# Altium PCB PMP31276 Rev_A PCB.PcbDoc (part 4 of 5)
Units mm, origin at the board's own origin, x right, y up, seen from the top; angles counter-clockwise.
Board outline 228.6 x 203.2 mm, 4 copper layers (Top Layer, Layer 1, Layer 2, Bottom Layer), stack 1.998 mm thick; 375 components, 187 nets, 994 pads, 546 vias.
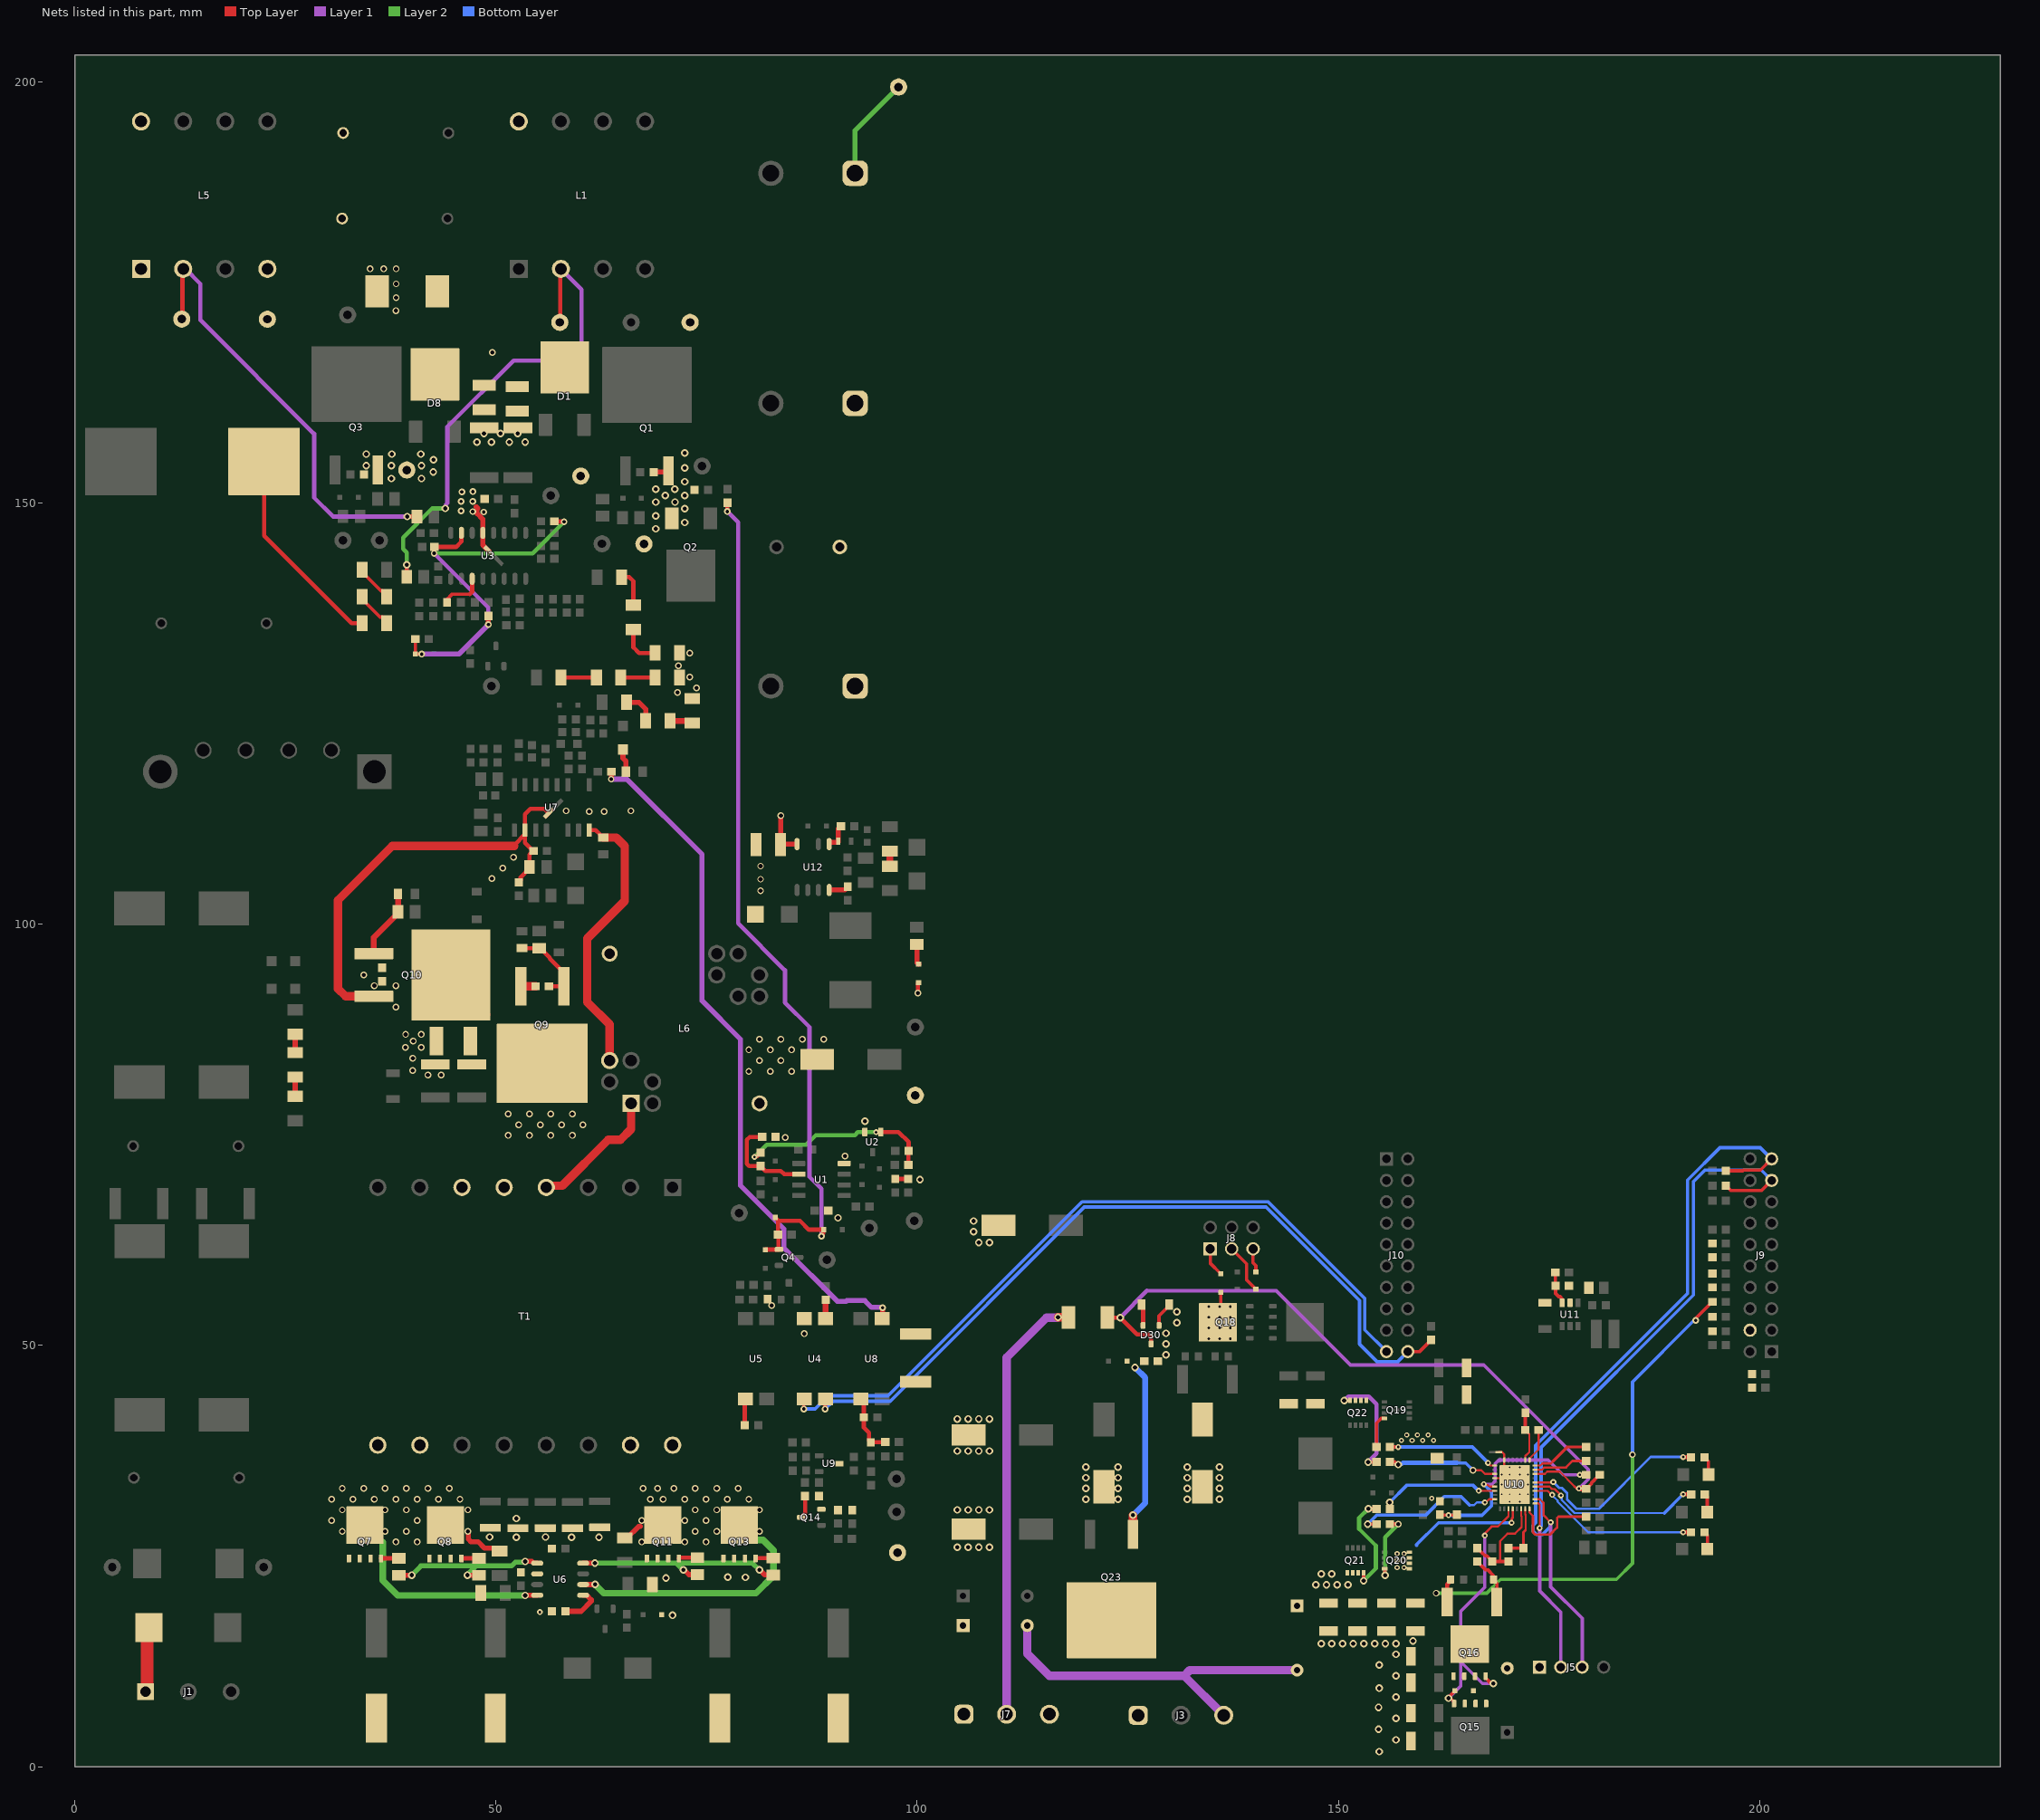
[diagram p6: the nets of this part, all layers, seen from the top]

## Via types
v1: diameter 0.8, hole 0.5, Top Layer to Bottom Layer, tented both sides, 185 vias
v2: diameter 0.9, hole 0.5, Top Layer to Bottom Layer, tented both sides, 166 vias
v3: diameter 0.6, hole 0.3, Top Layer to Bottom Layer, tented both sides, 64 vias
v4: diameter 0.8, hole 0.4, Top Layer to Bottom Layer, tented both sides, 55 vias
v5: diameter 0.7, hole 0.3, Top Layer to Bottom Layer, tented both sides, 55 vias
v6: diameter 0.5, hole 0.2, Top Layer to Bottom Layer, 16 vias
v7: diameter 0.9, hole 0.5, Top Layer to Bottom Layer, tented bottom, 3 vias
v8: diameter 0.864, hole 0.406, Top Layer to Bottom Layer, tented both sides, 2 vias

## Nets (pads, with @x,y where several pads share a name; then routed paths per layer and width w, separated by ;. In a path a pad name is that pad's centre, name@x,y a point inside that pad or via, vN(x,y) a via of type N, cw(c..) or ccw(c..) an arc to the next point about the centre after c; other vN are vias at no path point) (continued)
NetD21_2: D21.2 R73.1 | length 2.8
  Top Layer w0.6: D21.2@65.073,120.74 65.073,119.712 65.421,119.364 R73.1@65.421,118.11
NetD22_1: D22.1 Q15.4 Q16.4 U10.31 | length 34.3
  Top Layer w0.25: 168.691,28.509 168.966,28.509 170.191,29.734 U10.31@170.191,30.595
  Top Layer w0.3: v5@167.295,27.594 168.209,28.509 168.691,28.509
  Top Layer w0.4: Q15.4@163.743,7.485 163.743,7.685 163.395,8.032 163.164,8.032 v2(163.068,8.128) 163.068,8.225 D22.1@163.848,9.005 ; Q16.4@167.479,10.74 167.479,10.54 168.054,9.964 168.295,9.964 v7(168.391,9.868)
  Layer 1 w0.4: v2(163.068,8.128) 164.525,9.585 164.525,12.437 ; v5(167.386,27.432) 167.386,21.309 164.525,18.448 164.525,12.437 ; v7(168.391,9.868) 167.094,9.868 164.525,12.437
NetD22_2: D22.2 Q15.1 Q15.2 Q15.3 Q16.1 Q16.2 Q16.3
NetD25_2: D25.2 Q23.1 R113.2 | length 21.1
  Top Layer w0.4: D25.2@124.823,48.029 D25.2@124.923,48.129
  Top Layer w1: Q23.1@125.603,27.586 v2(125.603,29.845)
  Bottom Layer w0.7: v2(125.603,29.845) 127.078,31.32 127.078,46.17 v2(125.857,47.391)
NetD26_1: D26.1 R104.1 | length 2.2
  Top Layer w0.4: R104.1@193.486,32.309 193.503,32.309 193.778,32.034 D26.1@193.778,30.226
NetD27_1: D27.1 R105.1 | length 2.1
  Top Layer w0.4: R105.1@193.459,27.813 193.484,27.813 193.805,27.492 D27.1@193.805,25.832
NetD28_1: D28.1 R106.1 | length 2.2
  Top Layer w0.4: R106.1@193.459,36.703 193.484,36.703 193.924,36.263 D28.1@193.924,34.668
NetD29_1: D29.1 D30.2 | length 2.6
  Top Layer w0.5: D29.1@126.633,54.864 126.82,54.677 126.82,52.384 D30.2@126.811,52.375
NetD30_3: D30.3 R110.1 R111.2 R112.1 U10.8 | length 84.5
  Top Layer w0.25: U10.8@173.341,34.745 174.523,34.745 174.793,35.015 176.284,35.015 178.054,33.245
  Top Layer w0.3: 178.054,33.245 v5@178.312,32.987
  Top Layer w0.4: R111.2@179.412,32.987 179.437,32.987 180.058,33.608 180.058,33.702 180.34,33.985 180.34,33.991 180.987,34.638 R112.1@181.012,34.638
  Top Layer w0.5: R110.1@122.568,53.307 v2(124.093,53.307) 126.093,51.307 127.468,51.307 127.761,51.014 D30.3@127.761,50.175
  Top Layer w0.6: v5(178.562,33.02) 178.579,33.003 179.395,33.003 R111.2@179.412,32.987
  Layer 1 w0.4: 127.288,56.502 142.615,56.502 151.435,47.683 167.266,47.683 179.662,35.287 179.662,34.12 v5(178.562,33.02)
  Layer 1 w0.5: v2(124.093,53.307) 127.288,56.502
NetD31_1: D31.1 J8.1 | length 3.5
  Top Layer w0.4: J8.1@134.79,61.468 134.79,59.757 D31.1@136.043,58.504
NetD32_1: D32.1 J8.3 | length 6
  Top Layer w0.4: J8.3@137.33,61.468 139.107,59.691 139.107,57.776 D32.1@140.202,56.681
NetD33_1: D33.1 J8.5 | length 2.9
  Top Layer w0.4: J8.5@139.87,61.468 139.87,59.808 140.202,59.476 D33.1@140.202,58.701
NetD37_1: D37.1 R120.1 | length 2.4
  Top Layer w0.6: R120.1@99.968,97.614 99.968,95.441 D37.1@100.161,95.248
NetF1_1: F1.1 J1.1 | length 7.8
  Top Layer w1.5: J1.1@8.397,8.89 8.6,9.093 8.6,16.308 F1.1@8.802,16.51
NetJ2_2: J2.2 J3.3 J4.2 | length 43.4
  Layer 1 w1: J4.2@113.073,16.749 113.073,13.419 115.697,10.795 131.699,10.795 ; J3.3@136.398,6.096 131.699,10.795 ; J2.2@145.098,11.451 132.355,11.451 131.699,10.795
NetJ4_1: J4.1 J7.1 Q23.2
NetJ7_2: J7.2 R110.2 | length 51.7
  Top Layer w1: v2(116.713,53.34) 117.934,53.34 R110.2@117.968,53.307
  Layer 1 w1: J7.2@110.617,6.223 110.617,48.565 115.359,53.307 116.68,53.307 v2(116.713,53.34)
NetJ11_2: J11.2 Q16.5 Q16.6 Q16.7 Q16.8 Q16.9@165.574,14.54 R87.1 R88.2 R90.2 | length 6
  Top Layer w0.4: R90.2@166.497,24.346 166.497,24.321 167.445,23.373 167.715,23.373 168.388,22.7 168.388,22.227 168.39,22.225 168.39,22.075 168.44,22.025 168.576,22.025 168.811,21.791 R87.1@168.811,19.525
NetL6_1: L6.1 T1.4 | length 16
  Top Layer w1: T1.4@55.967,68.767 56.168,68.968 57.872,68.968 63.321,74.417 64.779,74.417 66.04,75.678 L6.1@66.04,78.74
NetQ7_4: Q7.4 R48.2 | length 2.1
  Top Layer w0.5: Q7.4@36.362,24.714 36.362,24.727 38.468,24.727 R48.2@38.481,24.74
NetQ8_4: Q8.4 R49.2 | length 2.1
  Top Layer w0.5: Q8.4@45.887,24.715 45.887,24.728 47.953,24.728 R49.2@47.965,24.74
NetQ9_1: Q9.1 R50.2 R51.2 R53.2 | length 9.6
  Top Layer w0.5: R51.2@53.086,97.171 53.094,97.163 55.11,97.163 R50.2@55.118,97.155 55.283,97.155 56.399,96.039 56.399,95.908 58.039,94.268 Q9.1@58.039,92.643 R53.2@56.299,92.643
NetQ10_1: Q10.1 R54.2 R56.2 R57.2 | length 8.3
  Top Layer w0.7: Q10.1@35.5,96.52 35.5,98.44 38.354,101.294 R54.2@38.354,101.459 38.362,101.467 38.362,103.595 R56.2@38.37,103.603
NetQ11_4: Q11.4 R55.2 | length 2.3
  Top Layer w0.5: Q11.4@71.722,24.715 71.722,24.818 R55.2@73.914,24.818
NetQ13_4: Q13.4 R59.2 | length 2.2
  Top Layer w0.5: Q13.4@80.812,24.714 80.812,24.765 R59.2@82.931,24.765
NetQ14_3: Q14.3 R83.2 | length 2.8
  Top Layer w0.5: Q14.3@86.228,29.596 86.428,29.596 86.478,29.646 86.478,29.846 86.694,30.062 R83.2@86.694,32.119
NetQ19_4: Q19.4 R92.1 | length 4.1
  Top Layer w0.4: R92.1@154.52,37.94 154.52,40.779 155.093,41.352 Q19.4@155.466,41.352
  Top Layer w0.5: R92.1@154.488,37.972 R92.1@154.52,37.94
NetQ20_4: Q20.4 R91.2 | length 8.5
  Top Layer w0.4: Q20.4@155.501,23.503 155.508,23.503 155.518,23.493 155.518,22.718 v7(155.536,22.7)
  Top Layer w0.5: R91.2@156.12,28.796 v1(157.101,28.796)
  Layer 2 w0.5: v7(155.536,22.7) 155.536,27.231 v1(157.101,28.796)
NetQ21_4: Q21.4 R94.1 | length 12.3
  Top Layer w0.4: v7(152.993,22.075) Q21.4@152.993,23.008
  Top Layer w0.5: v2(153.543,30.607) 153.56,30.59 154.503,30.59 R94.1@154.52,30.574
  Layer 2 w0.5: v7(152.993,22.075) 154.45,23.532 154.45,26.235 152.46,28.225 152.46,29.524 v2(153.543,30.607)
NetQ22_4: Q22.4 R95.1 | length 13.3
  Top Layer w0.4: v2(150.693,43.47) Q22.4@151.368,43.47 ; v2(153.528,36.162) R95.1@154.52,36.162
  Layer 1 w0.5: v2(150.693,43.47) 150.727,43.47 151.189,43.932 153.632,43.932 154.52,43.045 154.52,37.154 v2(153.528,36.162)
NetR8_1: R8.1 R9.2 | length 2.2
  Top Layer w0.6: R9.2@26.162,84.762 R8.1@26.162,86.942
NetR9_1: R9.1 R14.2 | length 2.3
  Top Layer w0.6: R14.2@26.162,79.574 R9.1@26.162,81.862
NetR10_1: R10.1 R13.1 R19.2 U2.1 | length 23.7
  Top Layer w0.5: v5(80.694,72.375) 80.732,72.413 80.965,72.413 81.419,72.867 R19.2@81.419,72.892 ; v5(95.123,75.311) 95.136,75.324 95.66,75.324 U2.1@95.674,75.338 97.79,75.338 98.99,74.138 R10.1@98.99,73.1 98.969,73.079 98.969,71.467 R13.1@98.947,71.446
  Layer 2 w0.5: v5(80.694,72.375) 82.15,73.831 86.829,73.831 87.966,74.969 92.591,74.969 92.933,75.311 v5(95.123,75.311)
NetR11_1: R11.1 R16.2 | length 4.1
  Top Layer w0.5: R16.2@64.823,129.286 R11.1@68.908,129.286
NetR16_1: R16.1 R21.2 | length 4.2
  Top Layer w0.5: R21.2@57.711,129.286 R16.1@61.923,129.286
NetR19_1: R19.1 R24.2 U1.6 | length 11.5
  Top Layer w0.5: R24.2@81.585,74.752 80.121,74.752 79.765,74.396 79.765,71.585 80.057,71.292 R19.1@81.419,71.292 81.419,71.267 81.644,71.042 81.669,71.042 81.99,70.721 83.817,70.721 84.21,70.329 U1.6@85.946,70.329
NetR25_1: R25.1 R27.2 | length 4.5
  Top Layer w0.4: R27.2@34.11,138.867 34.11,138.592 36.247,136.455 36.56,136.455 37.01,136.005 R25.1@37.01,135.73
NetR27_1: R27.1 R29.2 | length 4.6
  Top Layer w0.4: R29.2@34.11,142.091 34.11,141.816 36.334,139.592 36.56,139.592 37.01,139.142 R27.1@37.01,138.867
NetR32_1: R32.1 U4.1 | length 2.2
  Top Layer w0.7: U4.1@89.13,53.188 R32.1@89.13,55.423
NetR39_1: R39.1 U5.1 | length 3.2
  Top Layer w0.5: R39.1@79.535,40.513 79.535,43.593 U5.1@79.605,43.663
NetR40_2: R40.2 U3.3 | length 4.9
  Top Layer w0.4: R40.2@44.196,138.62 44.196,138.595 44.765,139.164 46.863,139.164
  Top Layer w0.5: 46.863,139.164 47.17,139.471 U3.3@47.17,141.011
NetR43_1: R43.1 R44.2 | length 4.4
  Top Layer w0.5: R43.1@64.915,141.205 65.815,141.205 66.311,140.709 R44.2@66.311,137.886
NetR44_1: R44.1 R45.2 | length 5
  Top Layer w0.5: R44.1@66.311,134.986 66.311,132.859 66.963,132.207 R45.2@68.908,132.207
NetR61_2: R61.2 U6.5 | length 4.9
  Top Layer w0.6: R61.2@58.235,18.44 60.104,18.44 61.317,19.653 61.317,19.795 60.767,20.345 U6.5@60.342,20.345
NetR66_1: R66.1 R68.2 | length 2.7
  Top Layer w0.7: R68.2@70.643,124.149 73.029,124.149 R66.1@73.279,123.899
NetR68_1: R68.1 R71.2 | length 4
  Top Layer w0.6: R71.2@65.495,126.352 66.958,126.352 67.799,125.511 67.799,124.204 R68.1@67.743,124.149
NetR70_1: R70.1 R72.1 R78.2 U8.1 | length 7.4
  Top Layer w0.5: U8.1@93.322,43.663 93.666,43.319 R78.2@93.666,41.478 93.666,40.253 94.268,39.651 94.268,38.71 R70.1@94.493,38.485 94.525,38.517 96.195,38.517 R72.1@96.227,38.549
NetR82_2: R82.2 U8.3 | length 82.1
  Top Layer w0.6: v4(63.674,117.225) 63.68,117.231 63.68,118.104 R82.2@63.686,118.11 ; U8.3@95.862,53.188 95.873,53.199 95.873,54.471 v4(95.885,54.483)
  Layer 1 w0.6: v4(63.674,117.225) 65.525,117.225 74.454,108.296 74.454,90.914 79.035,86.333 79.035,68.972 84.163,63.844 84.163,61.602 90.539,55.227 91.547,55.227 91.647,55.327 93.787,55.327 94.593,54.521 95.847,54.521 v4(95.885,54.483)
NetR90_1: R90.1 R99.1 R100.2 U10.34 | length 12.2
  Top Layer w0.25: 169.228,24.346 169.199,24.374 169.199,26.777 170.075,27.653 170.957,27.653 171.75,28.446 171.75,29.702 171.691,29.761 U10.34@171.691,30.595
  Top Layer w0.4: R90.1@166.497,25.946 166.497,25.921 167.118,25.3 167.16,25.3 167.443,25.017 167.629,25.017 168.275,24.371 R99.1@168.275,24.346 169.228,24.346 R100.2@170.18,24.346
NetR91_1: R91.1 U10.27 | length 18.2
  Top Layer w0.25: v5(167.386,31.369) 167.508,31.369 167.883,31.745 U10.27@168.541,31.745
  Top Layer w0.4: v2(153.475,28.796) R91.1@154.52,28.796
  Bottom Layer w0.25: 165.574,31.049 166.104,31.049 166.424,31.369 v5(167.386,31.369)
  Bottom Layer w0.4: v2(153.475,28.796) 154.528,29.849 160.363,29.849 162.575,32.061 164.562,32.061 165.574,31.049
NetR92_2: R92.2 U10.19 | length 13.4
  Top Layer w0.25: v5(167.767,36.068) 167.767,35.997 168.02,35.745 U10.19@168.541,35.745
  Top Layer w0.4: R92.2@156.12,37.94 v5(157.101,37.94)
  Bottom Layer w0.4: v5(157.101,37.94) 165.895,37.94 v5(167.767,36.068)
NetR94_2: R94.2 U10.25 | length 14.4
  Top Layer w0.25: v5(166.661,32.745) U10.25@168.541,32.745
  Top Layer w0.4: v2(156.083,31.369) 156.101,31.351 156.101,30.592 R94.2@156.12,30.574
  Bottom Layer w0.4: v2(156.083,31.369) 158.109,33.395 166.011,33.395 v5(166.661,32.745)
NetR95_2: R95.2 U10.21 | length 13.2
  Top Layer w0.25: v1(165.989,35.179) 166.971,35.179 167.405,34.745 U10.21@168.541,34.745
  Top Layer w0.5: R95.2@156.12,36.162 156.689,36.162 156.992,35.858 v2(157.101,35.858)
  Bottom Layer w0.4: 164.084,36.068 164.101,36.051 165.117,36.051 v1(165.989,35.179)
  Bottom Layer w0.5: v2(157.101,35.858) 157.177,35.935 157.546,35.935 157.679,36.068 164.084,36.068
NetR100_1: R100.1 R103.2 U10.35 | length 6.6
  Top Layer w0.25: 172.171,28.034 172.229,28.092 172.229,29.9 172.191,29.938 U10.35@172.191,30.595
  Top Layer w0.3: R103.2@171.958,25.946 171.958,27.821 172.171,28.034
  Top Layer w0.4: R100.1@170.18,25.946 R103.2@171.958,25.946
NetR101_2: R101.2 R102.1 U10.12 | length 6.2
  Top Layer w0.25: R102.1@172.173,39.972 172.198,39.972 172.548,39.622 172.548,39.597 172.664,39.48 172.664,37.335 172.191,36.862 U10.12@172.191,36.395
  Top Layer w0.4: R102.1@172.082,40.063 R102.1@172.173,39.972 172.192,39.991 172.192,41.979 R101.2@172.212,41.999
NetR102_2: R102.2 U10.11 | length 4
  Top Layer w0.25: U10.11@172.691,36.395 172.691,36.57 173.773,37.652 R102.2@173.773,39.972
NetR104_2: R104.2 U10.5 | length 21.1
  Top Layer w0.25: U10.5@173.341,33.245 175.056,33.245 175.339,32.962 175.678,32.962 176.413,32.227 v5(176.413,32.185)
  Top Layer w0.5: v5(190.924,32.335) 190.937,32.322 191.873,32.322 R104.2@191.886,32.309
  Bottom Layer w0.25: v5(176.413,32.185) 176.499,32.098 176.499,31.653 178.041,30.111 188.701,30.111
  Bottom Layer w0.4: 188.701,30.111 v5(190.924,32.335)
NetR105_2: R105.2 U10.4 | length 20.7
  Top Layer w0.25: U10.4@173.341,32.745 174.848,32.745 175.335,32.258 v5(175.387,32.258)
  Top Layer w0.5: v5(190.924,27.821) 190.928,27.817 191.855,27.817 R105.2@191.859,27.813
  Bottom Layer w0.25: v5(175.387,32.258) 175.387,32.215 176.02,31.582 176.02,31.455 179.655,27.821 v5(190.924,27.821)
NetR106_2: R106.2 U10.6 | length 22.9
  Top Layer w0.25: U10.6@173.341,33.745 175.477,33.745 v5(175.514,33.782)
  Top Layer w0.3: R106.2@191.806,36.756 R106.2@191.859,36.703
  Top Layer w0.5: v5(190.924,36.756) R106.2@191.806,36.756
  Bottom Layer w0.3: v5(175.514,33.782) 176.204,33.092 176.535,33.092 177.148,32.48 177.148,31.716 178.25,30.615 180.922,30.615 187.071,36.764 190.916,36.764 v5(190.924,36.756)
NetR107_2: R107.2 U10.36 | length 10.9
  Top Layer w0.25: U10.36@172.691,30.595 172.691,30.16 173.101,29.749
  Top Layer w0.3: 173.101,29.749 173.101,27.819 173.366,27.553 175.132,27.553 175.962,28.383 175.962,29.503 176.143,29.685 R107.2@179.412,29.685
NetR108_2: R108.2 U10.9 | length 6.5
  Top Layer w0.25: U10.9@173.341,35.245 174.161,35.245 174.411,35.494 176.987,35.494 177.038,35.545
  Top Layer w0.3: 177.038,35.545 177.782,36.289 R108.2@179.412,36.289
NetR109_2: R109.2 U10.10 | length 7
  Top Layer w0.25: U10.10@173.341,35.745 173.985,35.745 174.212,35.972 175.197,35.972 175.477,36.252
  Top Layer w0.35: 175.477,36.252 177.165,37.94 R109.2@179.412,37.94
NetR114_1: R114.1 R115.2 U11.3 | length 4
  Top Layer w0.4: R114.1@175.754,58.67 175.767,58.658 175.767,57.1 R115.2@175.779,57.088 175.779,56.166 176.16,55.785 176.32,55.785 176.554,55.551 U11.3@176.554,55.06
NetR116_2: R116.2 R117.1 | length 1.8
  Top Layer w0.8: R117.1@96.749,106.881 R116.2@96.749,108.67
NetR118_2: R118.2 R132.2 U12.5 | length 3.3
  Top Layer w0.6: U12.5@89.549,109.512 89.549,109.709 90.587,109.709 90.633,109.755 R118.2@90.633,109.854 90.633,111.329 90.743,111.439 90.743,111.464 90.918,111.639 R132.2@90.943,111.639
NetR119_2: R119.2 U12.4 | length 2.4
  Top Layer w0.6: U12.4@89.549,104.062 91.383,104.062 91.748,104.427 R119.2@91.748,104.452
NetT1_5: T1.5 T1.6
PGND: C4.2 C14.2 C15.2 C16.2 C17.2 C19.2 C32.2 C43.1 C44.1 C48.2 C49.2 C50.2 C97.2 C98.2 D36.2 D37.2 L6.13 L6.14 NT2.1 NT3.1 Q1.3 Q2.3 Q3.3 Q10.3 R2.1 R4.1 R5.1 R17.1 R20.1 R24.1 R47.2 R57.1 RT1.1 TP4.1 TP7.1 TP9.1 TP15.1 TP27.1 U1.4 U2.2 U3.13 U4.2 U7.10 | length 64.5
  Top Layer w0.5: 52.181,109.292 52.181,109.425 U7.10@53.451,110.695 ; C49.2@52.705,104.977 52.93,105.202 52.93,105.597 53.975,106.642 C48.2@53.975,106.807 53.975,108.267 C50.2@54.42,108.712 ; U7.10@53.401,111.22 U7.10@53.451,111.17 ; C50.2@54.445,108.712 C50.2@54.42,108.712 ; NT3.1@55.891,112.817 55.897,112.817 NT3.1@56.256,113.177 55.717,113.715 54.091,113.715 53.451,113.075 U7.10@53.451,111.17 ; R20.1@97.389,69.761 C17.2@98.933,69.761 ; v1(100.103,91.834) 100.103,92.89 100.111,92.898 100.111,92.998 D37.2@100.161,93.048 ; U7.10@53.451,110.695 U7.10@53.451,111.17 ; U7.10@53.451,110.695 53.451,109.681 C50.2@54.42,108.712
  Top Layer w0.6: 47.856,149.359 47.681,149.534 47.656,149.534 47.752,149.438 47.752,148.774 48.44,148.086 U3.13@48.44,146.461 48.44,145.023 NT2.1@49.177,144.286 ; R2.1@68.722,153.67 70.318,153.67 Q1.3@70.462,153.814
  Top Layer w1: Q10.3@35.5,91.44 32.155,91.44 31.25,92.345 31.25,102.841 37.701,109.292 52.181,109.292
  other v1: 86.585,51.395 82.718,54.754 91.419,72.463 84.321,74.681 41.912,82.112 43.483,82.112 80.01,82.55 82.55,82.55 85.09,82.55 40.089,82.621 81.28,83.82 83.82,83.82 40.126,84.076 80.01,85.09 82.55,85.09 85.09,85.09 39.243,85.393 41.122,85.393 40.182,86.125 81.28,86.36 83.82,86.36 86.36,86.36 88.9,86.36 39.274,86.917 41.142,86.917 38.1,90.17 35.56,92.71 38.1,92.71 34.29,93.98 81.407,103.992 81.407,105.345 49.53,105.41 50.8,106.68 81.407,106.906 52.07,107.95 62.845,113.368 61.049,113.395 58.343,113.464 66.017,113.464
  other v2: 90.602,65.145 100.33,69.668 93.787,76.63 68.961,146.939 72.39,147.701 68.961,148.463 72.39,149.352 68.961,150.114 71.247,150.114 70.104,150.876 72.39,150.876 68.961,151.656 71.232,151.656 72.39,152.539 37.592,152.908 41.148,152.908 42.545,153.67 72.39,154.178 34.601,154.433 37.592,154.432 41.148,154.432 42.564,155.14 34.601,155.811 37.619,155.812 41.069,155.811 72.39,155.956 47.752,157.226 49.462,157.226 51.585,157.226 53.467,157.226 50.546,158.242 52.578,158.242 48.575,158.271
  other v4: 48.554,148.932 47.236,148.985 45.847,149.058 45.847,150.195 47.236,150.195 45.947,151.332 47.265,151.354
REG_N: C87.2 R98.1 R112.2 U10.24 | length 27.3
  Top Layer w0.25: v5(167.259,33.528) 167.345,33.442 167.74,33.442 167.916,33.266 168.093,33.266 168.115,33.245 U10.24@168.541,33.245
  Top Layer w0.4: C87.2@162.051,29.901 162.077,29.875 163.048,29.875 v5(163.074,29.849) 163.1,29.875 164.057,29.875 R98.1@164.083,29.901 ; v5(178.662,34.638) R112.2@179.412,34.638
  Layer 1 w0.4: v5(167.259,33.528) 168.232,33.528 168.617,33.913 168.617,35.958 169.053,36.395 174.904,36.395 176.661,34.638 v5(178.662,34.638)
  Bottom Layer w0.4: v5(163.074,29.849) 163.097,29.826 167.042,29.826 168.165,30.949 168.165,32.622 v5(167.259,33.528)
SCL: J5.2 J9.9 R121.1 U10.1 | length 86.1
  Top Layer w0.25: U10.1@173.341,31.245 173.748,31.245 173.895,31.098 v5(173.895,28.321)
  Top Layer w0.4: R121.1@195.999,68.961 196.024,68.961 196.603,68.382 200.208,68.382 J9.9@201.422,69.596
  Layer 1 w0.4: v5(173.895,28.321) 173.895,20.846 176.403,18.337 J5.2@176.403,11.815
  Bottom Layer w0.4: v5(173.895,28.321) 173.895,28.402 174.058,28.565 174.058,37.884 192.151,55.977 192.151,69.452 193.509,70.81 200.208,70.81 J9.9@201.422,69.596
SDA: J5.3 J9.10 R122.1 U10.2 | length 93.1
  Top Layer w0.25: U10.2@173.341,31.745 173.925,31.745 174.373,31.296 174.373,29.821 v5(175.195,28.999)
  Top Layer w0.4: R122.1@195.999,70.739 198.004,70.739 198.074,70.81 200.096,70.81 J9.10@201.422,72.136
  Layer 1 w0.4: v5(175.195,28.999) 175.195,21.347 178.943,17.599 J5.3@178.943,11.815
  Bottom Layer w0.4: v5(175.195,28.999) 175.138,28.942 175.138,28.463 174.217,27.542 173.525,27.542 173.116,27.951 173.116,28.643 173.429,28.956 173.429,38.144 191.451,56.166 191.451,69.64 195.28,73.469 200.089,73.469 J9.10@201.422,72.136
SGND: C8.1 C12.1 C34.1 C35.2 C36.2 C37.2 C38.2 C39.1 C40.1 C41.1 C44.2 C45.1 C46.2 C47.1 C63.2 C64.2 C65.2 C66.2 C67.2 C68.2 C71.2 C72.2 C73.2 C74.2 C75.2 C76.2 C77.2 C78.2 C79.2 C84.2 C87.1 C88.2 C89.2 C90.2 C92.1 C93.2 C99.2 C100.1 C101.2 C102.2 C103.2 D18.2 D29.2 D30.1 J3.1 J5.1 J7.3 J9.22 J10.20 NT1.1 Q7.1 Q7.2 Q7.3 Q8.1 Q8.2 Q8.3 Q11.1 Q11.2 Q11.3 Q13.1 Q13.2 Q13.3 Q14.2 Q21.1 Q21.2 Q21.3 Q22.1 Q22.2 Q22.3 R61.1 R85.1 R86.2 R113.1 R115.1 R125.2 R127.2 R128.2 TP24.1 U4.3 U6.2 U9.3 U10.17 U10.22 U10.37 U11.2 | length 96.5
  Top Layer w0.25: U10.22@168.541,34.245 U10.37@169.391,34.245 ; NT1.1@169.037,37.338 169.039,37.336 169.433,37.336 169.691,37.078 U10.17@169.691,36.395 U10.37@169.691,35.345
  Top Layer w0.4: v4(86.538,42.455) 86.538,43.611 U4.3@86.59,43.663 ; D30.1@128.711,52.375 128.711,53.515 129.907,54.711 D29.2@129.907,54.864
  Bottom Layer w0.4: v4(86.538,42.455) 87.893,42.455 89.451,44.013 96.539,44.013 119.582,67.056 141.668,67.056 153.137,55.587 153.137,51.841 J10.20@155.702,49.276
  other v2: 154.845,1.778 156.845,3.175 154.766,4.448 156.845,5.715 154.77,7.04 156.845,8.255 154.864,9.312 156.845,10.795 154.845,12.079 156.845,13.335 147.955,14.605 149.225,14.605 150.495,14.605 151.765,14.605 153.035,14.605 154.305,14.605 155.575,14.605 156.845,14.605 158.85,14.935 70.967,17.965 147.32,21.59 148.59,21.59 149.86,21.59 151.13,21.59 70.182,22.394 77.521,22.486 79.594,22.478 147.955,22.86 149.225,22.86 104.775,26.035 106.045,26.035 107.315,26.035 108.585,26.035 52.415,27.228 58.985,27.228 62.223,27.228 49.244,27.251 55.885,27.251 52.415,29.457 104.775,30.48 106.045,30.48 107.315,30.48 108.585,30.48 120.015,31.75 123.825,31.75 132.08,31.75 135.89,31.75 120.015,33.02 123.825,33.02 132.08,33.02 135.89,33.02 120.015,34.29 123.825,34.29 132.08,34.29 135.89,34.29 120.015,35.56 123.825,35.56 132.08,35.56 135.89,35.56 104.775,37.465 106.045,37.465 107.315,37.465 108.585,37.465 104.775,41.275 106.045,41.275 107.315,41.275 108.585,41.275 129.54,48.895 129.54,50.165 129.54,51.435 130.81,52.705 130.81,53.975 107.315,62.23 108.585,62.23 106.68,63.5 106.68,64.77
  other v3: 161.092,31.855 157.48,38.735 158.75,38.735 160.02,38.735 161.29,38.735 158.115,39.37 159.385,39.37 160.655,39.37
  other v5: 55.207,18.345
  other v6: 170.326,31.445 171.556,31.445 169.391,32.335 170.326,32.335 171.556,32.335 172.491,32.335 169.391,33.495 170.326,33.495 171.556,33.495 172.491,33.495 169.391,34.655 170.326,34.655 171.556,34.655 172.491,34.655 170.326,35.545 171.556,35.545
SW: C51.1 L6.11 Q9.3 Q10.4 R53.1 U7.16 | length 44.5
  Top Layer w0.5: Q9.3@52.959,92.643 Q9.3@53.086,92.516 ; U7.16@61.071,111.17 61.836,111.17 62.34,110.667 62.34,110.542 62.59,110.292 C51.1@62.715,110.292
  Top Layer w1: Q10.4@44.65,93.98 44.65,93.481 Q10.4@48.85,89.281 ; Q9.3@52.959,92.643 R53.1@54.699,92.643 ; C51.1@62.715,110.292 64.255,110.292 65.28,109.267 65.28,102.763 ; L6.11@63.5,83.82 63.5,88.089 60.827,90.762 60.827,98.311 65.28,102.763 ; 65.28,105.431 65.28,102.763
SYSTEM: C68.1 C71.1 C72.1 C73.1 C74.1 D31.2 J2.1 Q18.5 Q18.6 Q18.7 Q18.8 Q18.9@135.699,52.757 Q20.5 Q20.6 Q20.7 Q20.8 Q20.9 R87.2 R89.2 R130.2 U10.32 | length 78.5
  Top Layer w0.25: v5(170.568,28.96) 170.608,28.999 170.608,29.474 170.691,29.557 U10.32@170.691,30.595
  Top Layer w0.4: v5(135.89,54.61) 136.043,54.763 D31.2@136.043,56.304 ; v4(192.405,52.959) 192.482,53.036 192.482,53.279 194.374,55.171 R130.2@194.399,55.171
  Top Layer w0.5: R87.2@162.911,19.525 162.913,19.527 162.913,21.656 163.333,22.075 R89.2@163.333,22.225
  Layer 2 w0.4: v1(161.599,20.594) 167.613,20.594 169.246,22.227 183.009,22.227 184.912,24.13 v4(184.912,37.038)
  Bottom Layer w0.4: 159.294,26.253 159.294,26.359 161.894,28.96 v5(170.568,28.96) ; v4(184.912,37.038) 184.912,45.663 v4@192.211,52.962
  other v3: 156.972,23.622 157.788,23.622 156.971,24.478 157.788,24.478 156.972,25.273 157.788,25.273
  other v5: 134.62,50.8 135.89,50.8 137.16,50.8 134.62,52.07 135.89,52.07 137.16,52.07 134.62,53.34 135.89,53.34 137.16,53.34 134.62,54.61 137.16,54.61
VAC: C5.2 C7.2 D4.2 L1.8 L2.2 L5.1 L5.4 L5.8 R25.2 TP2.1 | length 24.8
  Top Layer w0.5: L2.2@22.47,154.94 22.47,146.111 32.851,135.73 R25.2@34.11,135.73
  other v1: 38.1,172.841 38.146,174.371 38.146,176.022 35.07,177.8 36.65,177.8 38.146,177.8
VAC_OK_PRI: D10.2 D13.2 D14.1 Q4.1 R6.2 R12.1 | length 104.3
  Top Layer w0.5: v4(77.47,148.992) R6.2@77.47,150.031 ; D14.1@81.957,61.352 81.982,61.377 83.564,61.377 Q4.1@83.588,61.402 ; D13.2@83.16,65.195 83.488,64.866 ; R12.1@83.513,63.148 R12.1@83.488,63.148 ; Q4.1@83.788,61.402 Q4.1@83.588,61.402 ; v4(88.63,62.969) 88.63,63.05 88.869,63.29 88.869,63.694 D10.2@88.919,63.744 87.124,63.744 86.086,64.781 83.573,64.781 83.488,64.866 ; R12.1@83.488,63.148 83.538,63.098 83.538,61.452 Q4.1@83.588,61.402 ; R12.1@83.488,63.148 83.488,64.866
  Layer 1 w0.5: v4(77.47,148.992) 78.74,147.722 78.74,100.106 84.307,94.539 84.307,90.692 87.21,87.79 87.21,70.02 88.63,68.6 v4(88.63,62.969)
VAC_OK_SEC: J10.40 R131.1 U4.4 | length 94.8
  Top Layer w0.4: J10.40@158.242,49.276 159.649,49.276 161.006,50.633 R131.1@161.006,50.658
  Top Layer w0.5: v4(89.065,42.455) 89.065,43.597 U4.4@89.13,43.663
  Bottom Layer w0.4: v4(89.065,42.455) 89.065,42.456 89.993,43.385 96.799,43.385 119.842,66.427 141.408,66.427 152.508,55.327 152.508,50.164 154.61,48.062 157.028,48.062 J10.40@158.242,49.276
VDS1: Q7.5-6-7-8 Q8.5-6-7-8 R52.1 T1.9 T1.10 U6.4 | length 29
  Top Layer w0.6: v1(46.657,27.94) 46.695,27.902 46.695,27.022 47.008,26.709 47.876,26.709 48.655,25.93 49.794,25.93 50.144,25.58 R52.1@50.419,25.58 ; v2(53.467,20.32) 53.492,20.345 U6.4@54.892,20.345
  Layer 2 w0.6: 36.461,26.704 36.547,26.617
  Layer 2 w0.8: 36.547,26.617 36.547,22.098 38.326,20.32 v2(53.467,20.32)
  other v1: 38.1,26.67 40.64,26.67 31.75,27.94 36.83,27.94 39.37,27.94 30.48,29.21 40.64,29.21 31.75,30.48 36.83,30.48 39.37,30.48 46.657,30.48 30.48,31.75 33.02,31.75 35.56,31.75 38.1,31.75 40.64,31.75 43.18,31.75 45.72,31.75 31.75,33.02 34.29,33.02 36.83,33.02 39.37,33.02 41.91,33.02 44.45,33.02
VDS2: Q11.5-6-7-8 Q13.5-6-7-8 R62.1 T1.15 T1.16 U6.6 | length 32.1
  Top Layer w0.6: U6.6@60.342,21.615 61.742,21.615 v2(61.752,21.625) ; R62.1@65.28,27.131 65.555,27.131 66.938,28.513 67.142,28.513
  Layer 2 w0.8: v2(61.752,21.625) 61.752,21.614 62.774,20.592 80.874,20.592 82.931,22.649 82.931,25.69 81.714,26.907 80.662,26.907
  other v1: 67.31,26.67 72.39,26.67 74.93,26.67 73.66,27.94 76.2,27.94 81.28,27.94 67.31,29.21 72.39,29.21 74.93,29.21 73.66,30.48 76.2,30.48 81.28,30.48 68.33,31.75 69.85,31.75 72.39,31.75 74.93,31.75 77.47,31.75 80.01,31.75 67.48,33.02 69.182,33.02 71.12,33.02 73.66,33.02 76.2,33.02 78.74,33.02
VG1: R48.1 R49.1 U6.1 | length 20
  Top Layer w0.6: R48.1@38.481,22.708 38.493,22.721 39.993,22.721 v2(40.005,22.733) ; v2(46.609,22.733) 46.621,22.721 47.952,22.721 R49.1@47.965,22.708 ; v2(53.467,24.348) 53.49,24.371 54.251,24.371 54.467,24.155 U6.1@54.892,24.155
  Layer 2 w0.6: v2(40.005,22.733) 41.096,23.824 47.391,23.824 ; v2(46.609,22.733) 46.609,22.814 47.391,23.596 47.391,23.824 ; v2(53.467,24.348) 53.41,24.29 52.316,24.29 51.849,23.824 47.391,23.824
VG2: R55.1 R59.1 U6.8 | length 26.3
  Top Layer w0.6: U6.8@60.342,24.155 v2(61.742,24.155) ; v2(72.263,23.368) 72.344,23.368 72.919,22.793 73.907,22.793 R55.1@73.914,22.786 ; v2(81.28,23.368) 81.297,23.368 81.915,22.75 82.914,22.75 R59.1@82.931,22.733
  Layer 2 w0.6: v2(61.742,24.155) 71.395,24.155 ; v2(72.263,23.368) 72.182,23.368 71.395,24.155 ; v2(81.28,23.368) 81.242,23.368 80.455,24.155 71.395,24.155
Vpfc: C1.1 C2.1 C3.1 C4.1 C16.1 C32.1 C33.2 C97.1 D1.2 D4.1 D8.2 Q9.4 R11.2 R45.1 R66.2 TP1.1 U12.8 | length 17.9
  Top Layer w0.6: C97.1@83.753,109.458 83.95,109.458 C97.1@84.003,109.512 ; v1(83.823,112.893) 83.788,112.858 83.788,109.727 C97.1@84.003,109.512 ; U12.8@85.739,109.512 C97.1@84.003,109.512
  Layer 2 w0.6: C3.1@92.63,189.15 92.63,194.23 TP1.1@97.79,199.39
  other v1: 51.435,74.93 53.975,74.93 56.515,74.93 59.055,74.93 52.705,76.2 55.245,76.2 57.785,76.2 60.325,76.2 51.435,77.47 53.975,77.47 56.515,77.47 59.055,77.47 71.558,127.527 73.786,128.05 72.997,129.327 71.644,130.683 72.997,132.207 49.575,167.859
VREF: C28.2 D15.1 R36.2 R37.2 R38.1 U3.15 | length 47.5
  Top Layer w0.4: R38.1@40.418,133.858 40.431,133.845 40.431,132.098 D15.1@40.445,132.084 41.151,132.084 v4(41.172,132.064)
  Top Layer w0.5: v4(42.661,144.03) 42.671,144.04 42.671,144.78 C28.2@42.682,144.79 45.268,144.79 45.881,145.403 45.881,146.442 U3.15@45.9,146.461 ; R37.2@56.934,147.828 56.966,147.796 58.053,147.796 v4(58.085,147.763)
  Top Layer w0.6: v4(49.099,135.578) R36.2@49.099,136.614
  Layer 1 w0.5: v4(42.661,144.03) 49.099,137.593 v4(49.099,135.578)
  Layer 1 w0.6: v4(41.172,132.064) 45.585,132.064 v4(49.099,135.578)
  Layer 2 w0.5: v4(42.661,144.03) 54.352,144.03 v4(58.085,147.763)
ZCD_A: L5.2 R30.2 TP18.1 | length 52.9
  Top Layer w0.5: TP18.1@12.7,171.831 12.78,171.911 12.78,177.72 L5.2@12.86,177.8 ; v2(39.466,148.399) 40.6,148.399 R30.2@40.603,148.401
  Layer 1 w0.5: L5.2@12.86,177.8 13.131,177.8 14.909,176.022 14.909,171.725 28.41,158.224 28.41,150.649 30.66,148.399 v2(39.466,148.399)
ZCD_B: L1.2 R31.2 TP20.1 | length 57.5
  Top Layer w0.5: R31.2@39.403,141.248 39.409,141.254 39.409,142.652 v2(39.416,142.658) ; TP20.1@57.584,171.45 57.642,171.509 57.642,177.741 L1.2@57.701,177.8
  Layer 1 w0.5: v2(43.985,149.359) 44.062,149.436 44.062,149.82 44.221,149.979 44.221,159.058 52.085,166.922 58.427,166.922 60.151,168.646 60.151,175.35 L1.2@57.701,177.8
  Layer 2 w0.5: v2(39.416,142.658) 39.416,144.121 38.983,144.553 38.983,145.908 42.434,149.359 v2(43.985,149.359)
pads on no net: D1.1 D8.1 H1.1 H1.2 H2.0 H3.0 H4.0 H5.0 H6.0 H7.0 J3.2 J5.4 J9.2 J9.3 J9.4 J9.6 J9.7 J9.21 J9.23 J9.27 J9.28 J9.29 J9.30 J10.11 J10.12 J10.13 J10.14 J10.15 J10.16 J10.17 J10.18 J10.19 J10.31 J10.32 J10.33 J10.34 J10.35 J10.36 J10.37 L1.1 L1.6 L1.7 L5.6 L5.7 L6.2 L6.3 L6.4 L6.5 L6.6 L6.7 L6.8 L6.9 L6.10 L6.12 Q15.9@164.198,3.29 Q15.9@164.198,5.07 Q15.9@165.648,3.29 Q15.9@165.648,4.14 Q15.9@165.648,5.07 Q15.9@167.098,3.29 Q15.9@167.098,5.07 Q16.9@164.124,13.155 Q16.9@164.124,14.935 Q16.9@165.574,13.155 Q16.9@165.574,14.085 Q16.9@165.574,14.935 Q16.9@167.024,13.155 Q16.9@167.024,14.935 Q17.9@144.643,51.307 Q17.9@144.643,52.757 Q17.9@144.643,54.207 Q17.9@145.573,52.757 Q17.9@146.423,51.307 Q17.9@146.423,52.757 Q17.9@146.423,54.207 Q18.9@135.304,51.307 Q18.9@135.304,52.757 Q18.9@135.304,54.207 Q18.9@136.154,52.757 Q18.9@137.084,51.307 Q18.9@137.084,52.757 Q18.9@137.084,54.207 T1.3 T1.8 U2.3

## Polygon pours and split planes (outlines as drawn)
SGND on Top Layer "TOP_LAYER_SGND_P097" (solid, remove dead copper, pour order 97): 34 vertices, not listed, extent 29.782,0.723 101.878,46.736
15Vp on Top Layer "TOP_LAYER_15VP_P147" (solid, remove dead copper, pour order 147): 24 vertices, not listed, extent 88.484,81.774 101.878,106.226
NetC94_2 on Top Layer "TOP_LAYER_NETC94_2_P145" (solid, remove dead copper, pour order 145): 92.757,103.378 92.986,103.607 92.986,105.431 93.486,105.431 93.486,100.082 85.09,100.082 85.09,104.274 85.672,104.855 88.484,104.855 88.898,104.442 88.898,101.872 90.458,101.872 91.964,103.378
SW on Top Layer "TOP_LAYER_SW_P001" (solid, remove dead copper, pour order 1): 40.05,99.33 40.182,99.33 61.202,99.33 61.793,98.63 61.793,89.383 61.39,88.981 49.601,88.981 49.3,88.68 40,88.68
PGND on Top Layer "TOP_LAYER_PGND_P048" (solid, remove dead copper, pour order 48): 46.133,148.095 43.985,150.243 43.985,155.142 46.438,157.595 47.681,157.595 47.681,155.909 46.046,154.274 46.046,152.454 46.796,151.704 48.965,151.704 49.463,151.206 49.463,148.095
CS on Top Layer "TOP_LAYER_CS_P033" (solid, remove dead copper, pour order 33): 46.649,154.19 46.649,152.474 46.989,152.135 51.015,152.135 51.736,151.414 52.838,151.414 53.559,152.135 54.55,152.135 55.061,152.645 55.061,154.055 54.306,154.81 47.269,154.81
SGND on Top Layer "TOP_LAYER_SGND_P141" (solid, remove dead copper, pour order 141): 17 vertices, not listed, extent 98.392,15.71 111.936,66.138
SGND on Top Layer "TOP_LAYER_SGND_P139" (solid, remove dead copper, pour order 139): 127.961,47.404 128.929,47.404 131.401,49.876 131.401,55.435 130.533,56.304 129.361,56.304 128.384,55.327 128.236,55.327 127.761,54.852 127.761,47.604
SGND on Top Layer "TOP_LAYER_SGND_P138" (solid, remove dead copper, pour order 138): 25 vertices, not listed, extent 141.278,27.574 165.456,39.789
SGND on Top Layer "TOP_LAYER_SGND_P137" (solid, remove dead copper, pour order 137): 23 vertices, not listed, extent 140.574,20.669 156.024,44.712
SGND on Top Layer "TOP_LAYER_SGND_P136" (solid, remove dead copper, pour order 136): 98.199,4.045 108.23,4.045 109.263,5.078 109.263,8.736 111.139,10.612 129.179,10.612 135.503,16.935 160.53,16.935 160.597,16.867 160.597,15.419 160.58,15.419 159.486,14.325 159.486,1.332 158.877,0.723 95.745,0.723
SGND on Top Layer "TOP_LAYER_SGND_P003" (solid, remove dead copper, pour order 3): 135.209,30.371 136.674,31.837 136.674,35.781 135.621,36.835 132.535,36.835 131.064,35.363 131.064,31.947 132.639,30.371
SGND on Top Layer "TOP_LAYER_SGND_P135" (solid, remove dead copper, pour order 135): 123.459,30.353 124.924,31.818 124.924,35.763 123.871,36.816 120.785,36.816 119.314,35.345 119.314,31.928 120.889,30.353
SGND on Top Layer "TOP_LAYER_SGND_P134" (solid, remove dead copper, pour order 134): 169.226,35.711 172.639,35.711 172.686,35.665 172.686,31.325 172.636,31.275 169.246,31.275 169.196,31.325
SGND on Top Layer "TOP_LAYER_SGND_P133" (solid, remove dead copper, pour order 133): 197.67,42.037 199.898,44.265 199.898,62.484 196.85,65.532 190.118,65.532 186.01,69.64 169.843,69.64 163.449,63.246 163.449,42.728 164.14,42.037
NetJ4_1 on Top Layer "TOP_LAYER_NETJ4_1_P130" (solid, remove dead copper, pour order 130): 111.333,12.467 108.389,9.523 108.389,6.044 106.791,4.445 104.138,4.445 103.487,5.096 103.487,17.164 104.357,18.034 113.658,18.034 117.747,22.123 128.982,22.123 130.215,20.891 130.215,13.497 129.185,12.467
NetD25_2 on Top Layer "TOP_LAYER_NETD25_2_P129" (solid, remove dead copper, pour order 129): 126.892,46.828 127.468,47.404 127.468,48.731 127.345,48.854 124.71,48.854 124.46,48.604 124.46,47.437 125.069,46.828
BAT on Top Layer "TOP_LAYER_BAT_P127" (solid, remove dead copper, pour order 127): 18 vertices, not listed, extent 115.136,43.639 132.604,49.18
NetC75_1 on Top Layer "TOP_LAYER_NETC75_1_P125" (solid, remove dead copper, pour order 125): 136.165,44.024 143.979,44.024 145.275,45.32 143.954,46.64 143.954,48.943 143.192,48.181 135.956,48.181 135.477,47.702 135.477,44.712
NetC75_1 on Top Layer "TOP_LAYER_NETC75_1_P124" (solid, remove dead copper, pour order 124): 120.523,38.517 124.064,38.517 125.425,39.878 125.425,43.588 124.714,44.299 121.007,44.299 120.523,43.815
BAT on Top Layer "TOP_LAYER_BAT_P123" (solid, remove dead copper, pour order 123): 22 vertices, not listed, extent 111.633,19.048 122.143,66.877
NetC91_2 on Top Layer "TOP_LAYER_NETC91_2_P122" (solid, remove dead copper, pour order 122): 180.804,53.778 181.224,54.198 181.224,55.242 182.268,55.242 182.339,55.171 182.339,54.116 181.519,53.297 181.519,49.403 181.265,49.149 179.174,49.149 178.15,50.173 178.15,53.187 178.741,53.778
NetC92_2 on Top Layer "TOP_LAYER_NETC92_2_P120" (solid, remove dead copper, pour order 120): 171.8,51.707 173.431,50.075 177.029,50.075 177.798,50.844 177.798,52.765 177.677,52.886 172.376,52.886 171.8,52.31
3V3 on Top Layer "TOP_LAYER_3V3_P118" (solid, remove dead copper, pour order 118): 176.855,58.195 176.891,58.16 180.618,58.16 181.228,57.55 184.579,57.55 185.115,58.086 182.749,60.452 177.912,60.452 176.855,59.395
3V3 on Top Layer "TOP_LAYER_3V3_P117" (solid, remove dead copper, pour order 117): 200.152,47.084 200.152,44.29 200.373,44.069 201.803,44.069 202.692,44.958 202.692,49.906 202.184,50.414 200.829,50.414 200.152,49.737
3V3 on Top Layer "TOP_LAYER_3V3_P116" (solid, remove dead copper, pour order 116): 194.724,66.167 190.754,66.167 189.357,67.564 189.357,70.358 190.754,71.755 194.654,71.755 194.945,71.464 194.945,66.388
3V3 on Top Layer "TOP_LAYER_3V3_P113" (solid, remove dead copper, pour order 113): 181.969,49.308 184.593,49.308 185.699,50.414 185.699,57.502 184.531,58.67 181.293,58.67 180.912,58.289 180.912,55.807 181.228,55.492 182.494,55.492 182.719,55.267 182.719,54.253 181.969,53.503 181.969,53.397
SYSTEM on Top Layer "TOP_LAYER_SYSTEM_P112" (solid, remove dead copper, pour order 112): 23 vertices, not listed, extent 127.761,17.575 163.83,43.527
NetD22_2 on Top Layer "TOP_LAYER_NETD22_2_P110" (solid, remove dead copper, pour order 110): 167.748,6.89 164.87,6.89 164.563,7.196 164.563,9.312 164.096,9.779 163.743,9.779 163.333,10.189 163.333,11.148 163.477,11.292 166.382,11.292 166.705,10.969 166.705,10.198 167.898,9.005 167.898,7.04
+24V on Top Layer "TOP_LAYER_+24V_P109" (solid, remove dead copper, pour order 109): 160.481,14.935 160.019,14.472 160.019,2.414 161.417,1.016 171.233,1.016 172.171,1.954 172.171,4.878 171.08,5.969 163.261,5.969 162.88,6.35 162.88,14.217 162.162,14.935
+24V on Top Layer "TOP_LAYER_+24V_P004" (solid, remove dead copper, pour order 4): 177.954,25.024 177.389,25.589 177.389,28.122 177.897,28.63 180.09,28.63 180.212,28.509 180.212,25.499 179.737,25.024
NetC80_1 on Top Layer "TOP_LAYER_NETC80_1_P107" (solid, remove dead copper, pour order 107): 155.87,23.883 147.725,23.883 144.898,26.71 144.898,31.31 145.428,31.839 149.617,31.839 154.45,27.007 154.45,26.128 154.766,25.811 155.721,25.811 155.87,25.663
NetJ11_2 on Top Layer "TOP_LAYER_NETJ11_2_P106" (solid, remove dead copper, pour order 106): 164.305,20.349 164.305,18.052 163.144,16.891 163.144,12.368 163.321,12.192 168.545,12.192 168.75,11.987 168.75,10.948 169.246,10.452 171.008,10.452 171.406,10.85 171.406,19.989 170.195,21.2 165.155,21.2
BAT_SRC on Top Layer "TOP_LAYER_BAT_SRC_P105" (solid, remove dead copper, pour order 105): 18 vertices, not listed, extent 139.002,50.257 142.71,55.245
NetC75_1 on Top Layer "TOP_LAYER_NETC75_1_P103" (solid, remove dead copper, pour order 103): 28 vertices, not listed, extent 142.71,40.161 163.1,55.626
NetC81_1 on Top Layer "TOP_LAYER_NETC81_1_P101" (solid, remove dead copper, pour order 101): 20 vertices, not listed, extent 144.643,34.913 155.87,43.785
AGND on Top Layer "TOP_LAYER_AGND_P099" (solid, remove dead copper, pour order 99): 21 vertices, not listed, extent 160.748,23.293 184.15,41.334
NetC47_2 on Top Layer "TOP_LAYER_NETC47_2_P005" (solid, remove dead copper, pour order 5): 64.38,25.005 66.127,25.005 66.455,24.677 66.455,20.645 66.26,20.45 64.781,20.45 64.38,20.85 64.38,24.995
NetC34_2 on Top Layer "TOP_LAYER_NETC34_2_P006" (solid, remove dead copper, pour order 6): 49.519,23.26 49.519,20.626 50.432,19.713 51.579,19.713 51.881,20.016 51.881,22.734 51.319,23.296
+24V on Top Layer "TOP_LAYER_+24V_P009" (solid, remove dead copper, pour order 9): 65.351,9.271 69.22,9.271 69.667,9.718 69.667,13.742 68.83,14.579 66.039,14.579 64.456,12.996 64.456,10.166
+24V on Top Layer "TOP_LAYER_+24V_P010" (solid, remove dead copper, pour order 10): 73.995,10.795 73.624,11.166 73.624,19.347 74.057,19.78 78.787,19.78 79.632,18.936 79.632,11.433 78.994,10.795
+24Vsw on Top Layer "TOP_LAYER_+24VSW_P011" (solid, remove dead copper, pour order 11): 57.435,10.178 61.411,10.178 61.845,10.612 61.845,14.308 61.574,14.579 58.168,14.579 56.885,13.297 56.885,10.704 57.435,10.154
+24Vsw on Top Layer "TOP_LAYER_+24VSW_P015" (solid, remove dead copper, pour order 15): 88.089,10.795 87.719,11.166 87.719,19.347 88.151,19.78 92.882,19.78 93.726,18.936 93.726,11.433 93.088,10.795
+24Vsw on Top Layer "TOP_LAYER_+24VSW_P014" (solid, remove dead copper, pour order 14): 47.449,10.795 47.079,11.166 47.079,19.347 47.511,19.78 52.242,19.78 53.086,18.936 53.086,11.433 52.448,10.795
+24Vsw on Top Layer "TOP_LAYER_+24VSW_P018" (solid, remove dead copper, pour order 18): 33.352,10.795 32.982,11.166 32.982,19.347 33.414,19.78 38.145,19.78 38.989,18.936 38.989,11.433 38.351,10.795
VDS2 on Top Layer "TOP_LAYER_VDS2_P095" (solid, remove dead copper, pour order 95): 73.052,40.559 82.219,31.393 82.219,26.669 81.898,26.348 66.638,26.348 66.638,31.888 64.407,34.12 64.407,39.799 65.166,40.559
VDS1 on Top Layer "TOP_LAYER_VDS1_P094" (solid, remove dead copper, pour order 94): 33.712,40.57 29.782,36.64 29.782,27.27 30.693,26.359 47.246,26.359 47.246,30.668 43.539,34.375 43.539,38.338 41.307,40.57
+24Vsw on Top Layer "TOP_LAYER_+24VSW_P087" (solid, remove dead copper, pour order 87): 44.457,39.497 44.457,34.795 48.397,30.855 62.695,30.855 63.444,31.604 63.444,39.088 61.962,40.57 45.53,40.57
NetT1_5 on Top Layer "TOP_LAYER_NETT1_5_P086" (solid, remove dead copper, pour order 86): 45.212,66.847 51.432,66.847 52.619,68.034 52.619,69.553 51.435,70.737 45.083,70.737 44.069,69.723 44.069,67.99
NetC9_1 on Top Layer "TOP_LAYER_NETC9_1_P085" (solid, remove dead copper, pour order 85): 20.833,59.276 23.114,61.557 23.114,82.579 21.7,83.993 14.594,83.993 13.688,83.087 13.688,78.603 17.605,74.686 17.605,64.91 17.04,64.345 14.298,64.345 13.688,63.734 13.688,60.788 15.2,59.276
AGND2 on Top Layer "TOP_LAYER_AGND2_P019" (solid, remove dead copper, pour order 19): 19 vertices, not listed, extent 43.985,112.182 68.908,127.527
PGND on Top Layer "TOP_LAYER_PGND_P084" (solid, remove dead copper, pour order 84): 90.211,81.774 75.288,81.774 72.607,84.455 72.607,110.623 73.492,111.508 81.899,111.508 81.899,105.03 81.899,90.86 85.305,87.454 89.214,87.454 91.748,84.919 91.748,83.311
PGND on Top Layer "TOP_LAYER_PGND_P083" (solid, remove dead copper, pour order 83): 73.787,75.477 73.787,51.816 75.057,50.546 101.878,50.546 101.878,75.246 99.78,77.343 75.653,77.343
NetQ10_1 on Top Layer "TOP_LAYER_NETQ10_1_P020" (solid, remove dead copper, pour order 20): 38.931,104.328 38.931,100.677 37.92,99.666 37.92,95.247 36.941,94.268 35.866,94.268 34.884,95.25 33.156,95.25 32.731,95.675 32.731,98.951 36.846,103.066 36.846,104.483 37.348,104.985 38.402,104.985 38.953,104.433
PGND on Top Layer "TOP_LAYER_PGND_P074" (solid, remove dead copper, pour order 74): 71.628,85.837 63.103,85.837 61.927,84.661 61.927,79.356 58.249,75.677 32.098,75.677 30.052,77.722 30.052,103.845 36.195,109.988 52.097,109.988 52.93,110.821 52.93,113.181 53.718,113.969 67.878,113.969 71.628,110.22
15Vp-sw on Top Layer "TOP_LAYER_15VP-SW_P070" (solid, remove dead copper, pour order 70): 55.118,102.392 52.416,102.392 52.181,102.627 52.181,103.921 52.437,104.177 53.797,104.177 54.445,104.826 54.968,104.826 55.099,104.695 55.099,104.51
5Vp on Top Layer "TOP_LAYER_5VP_P002" (solid, remove dead copper, pour order 2): 17 vertices, not listed, extent 48,115.87 52.437,119.797
15Vp-sw on Top Layer "TOP_LAYER_15VP-SW_P066" (solid, remove dead copper, pour order 66): 55.484,111.87 55.484,107.98 55.327,107.823 55.327,105.291 55.797,104.822 56.738,104.822 57.261,105.345 57.261,111.48 56.871,111.87
NetC33_1 on Top Layer "TOP_LAYER_NETC33_1_P060" (solid, remove dead copper, pour order 60): 48.756,78.246 47.533,78.246 42.799,73.512 42.799,67.982 41.967,67.15 40,67.15 39.116,68.034 39.116,79.514 40.182,80.58 48.863,80.58 49.3,80.143 49.3,78.79
Vpfc on Top Layer "TOP_LAYER_VPFC_P059" (solid, remove dead copper, pour order 59): 17 vertices, not listed, extent 44.944,74.027 61.752,88.604
NetD2_2 on Top Layer "TOP_LAYER_NETD2_2_P057" (solid, remove dead copper, pour order 57): 67.046,155.213 67.683,154.577 67.683,147.287 67.476,147.08 66.475,147.08 66.311,147.244 66.311,150.934 65.723,151.522 64.931,151.522 64.177,152.276 64.177,154.645 64.745,155.213
EARTH on Top Layer "TOP_LAYER_EARTH_P056" (solid, remove dead copper, pour order 56): 9.622,64.828 16.142,64.828 16.761,65.447 16.761,68.303 16.129,68.935 9.608,68.935 9.271,68.599 9.271,65.179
